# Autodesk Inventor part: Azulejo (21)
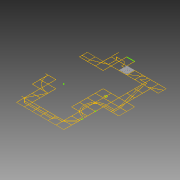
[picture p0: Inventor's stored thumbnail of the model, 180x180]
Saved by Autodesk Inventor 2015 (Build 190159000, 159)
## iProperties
Created: 2015-04
Part Number: Azulejo (21)
Material: Genérico
Document SubType Name: Modeling
Designer: Felipe
Density: 1 g/cm^3
Appearance: Padrão
Author: Felipe
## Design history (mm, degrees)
sketch "Sketch1"
  geometry: L1 (-1510, -7490)-(-1510, -6010); L2 (992.445, 7510)-(992.445, 8990); L3 (1012.445, 7510)-(1012.445, 8990); L4 (-3010, -1490)-(-3010, -10); L5 (-1510, 7490)-(-2990, 7490); L6 (-2990, 10)-(-1510, 10); L7 (-1510, -10)-(-2990, -10); L8 (-1510, -1490)-(-1510, -10); L9 (-10, 9010)-(-10, 10490); L10 (-10, 7510)-(-10, 8990); L11 (-10, 7490)-(-1490, 7490); L12 (-1490, 6010)-(-10, 6010); L13 (-10, 5990)-(-1490, 5990); L14 (-1490, -10)-(-1490, -1490); L15 (-1490, -1490)-(-10, -1490); L16 (-10, -1510)-(-1490, -1510); L17 (-10, -2990)-(-10, -1510); L18 (-10, -5990)-(-10, -4510); L19 (-1490, -7490)-(-10, -7490); L20 (10, 8990)-(10, 7510); L21 (1490, 7510)-(1490, 8990); L22 (10, 6010)-(1490, 6010); L23 (1490, 6010)-(1490, 7490); L24 (1490, 5990)-(10, 5990); L25 (4490, -6010)-(3010, -6010); L26 (10, -1510)-(10, -2990); L27 (10, -3010)-(10, -4490); L28 (10, -4510)-(10, -5990); L29 (10, -5990)-(1490, -5990); L30 (1490, -6010)-(10, -6010); L31 (10, -7490)-(1490, -7490); L32 (2990, 9010)-(2990, 10490); L33 (1510, 8990)-(1510, 7510); L34 (1510, 7510)-(2990, 7510); L35 (2990, 7490)-(1510, 7490); L36 (1510, 7490)-(1510, 6010); L37 (1510, -5990)-(2990, -5990); L38 (2990, -6010)-(1510, -6010); L39 (1510, -7490)-(2990, -7490); L40 (3010, 10490)-(3010, 9010); L41 (3010, 9010)-(4490, 9010); L42 (4490, 8990)-(3010, 8990); L43 (4490, 7490)-(3010, 7490); L44 (4490, 1510)-(4490, 2990); L45 (4490, 10)-(4490, 1490); L46 (4490, -1490)-(4490, -10); L47 (4490, -2990)-(4490, -1510); L48 (3010, -5990)-(4490, -5990); L49 (3010, -7490)-(4490, -7490); L50 (4510, 9010)-(5990, 9010); L51 (5990, 8990)-(4510, 8990); L52 (4510, 7510)-(5990, 7510); L53 (5990, 7490)-(4510, 7490); L54 (4510, 3010)-(5990, 3010); L55 (5990, 2990)-(4510, 2990); L56 (4510, 2990)-(4510, 1510); L57 (4510, 1510)-(5990, 1510); L58 (5990, 1510)-(5990, 1740.185); L59 (5990, 1760.2)-(5990, 2259.8); L60 (5990, 2279.815)-(5990, 2990); L61 (5990, 1490)-(4510, 1490); L62 (4510, 1490)-(4510, 10); L63 (4510, 10)-(5990, 10); L64 (5990, 10)-(5990, 1490)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; A1 r 250 centre (6000, 2010) between (5990, 2259.8) and (5990, 1760.2); A2 r 250 centre (6000, 2010) between (6010, 1760.2) and (6010, 2259.8); A3 r 270 centre (6000, 2010) between (5990, 2279.815) and (5990, 1740.185); A4 r 270 centre (6000, 2010) between (6010, 1740.185) and (6010, 2279.815); A5 r 3010.017 centre (0, 0) between (-1490, -2615.358) and (-346.554, -2990); A6 r 2990.017 centre (0, 0) between (-1490, -2592.316) and (-10, -2990); A7 r 3010.017 centre (0, 0) between (-2603.863, -1510) and (-1510, -2603.863); A8 r 2990.017 centre (0, 0) between (-2580.717, -1510) and (-1510, -2580.717); A9 r 3010.017 centre (0, 0) between (-2990, -346.554) and (-2615.358, -1490); A10 r 2990.017 centre (0, 0) between (-2990, -10) and (-2592.316, -1490); A11 r 2131.367 centre (7500, -1500) between (7490, 631.344) and (6010, 24.017); A12 r 2131.367 centre (7500, -1500) between (5975.983, -10) and (5368.656, -1490); A13 r 2131.367 centre (7500, -1500) between (5368.656, -1510) and (5975.983, -2990); A14 r 2131.367 centre (7500, -1500) between (6010, -3024.017) and (7190, -3608.703); A15 r 1831.367 centre (7500, -1500) between (7490.321, 331.342) and (6463.753, 10); A16 r 1831.367 centre (7500, -1500) between (6435.196, -10) and (6010, -435.196); A17 r 1831.367 centre (7500, -1500) between (5990, -463.753) and (5668.66, -1490); A18 r 1831.367 centre (7500, -1500) between (5668.66, -1510) and (5990, -2536.247); A19 r 1831.367 centre (7500, -1500) between (6010, -2564.804) and (6435.196, -2990); A20 r 1831.367 centre (7500, -1500) between (6463.753, -3010) and (7490, -3331.34); A21 r 2111.367 centre (7500, -1500) between (7490.047, 611.344) and (6024.272, 10); A22 r 2111.367 centre (7500, -1500) between (5990, -24.272) and (5388.656, -1490); A23 r 2111.367 centre (7500, -1500) between (5388.656, -1510) and (5990, -2975.728); A24 r 2111.367 centre (7500, -1500) between (6024.272, -3010) and (7210, -3591.357); A25 r 1811.367 centre (7500, -1500) between (7490.374, 311.342) and (6499.524, 10); A26 r 1811.367 centre (7500, -1500) between (6469.975, -10) and (6010, -469.975); A27 r 1811.367 centre (7500, -1500) between (5990, -499.524) and (5688.66, -1490); A28 r 1811.367 centre (7500, -1500) between (5688.66, -1510) and (5990, -2500.476); A29 r 1811.367 centre (7500, -1500) between (6010, -2530.025) and (6469.975, -2990); A30 r 1811.367 centre (7500, -1500) between (6499.524, -3010) and (7490, -3311.34); A31 r 449.871 centre (7499.449, -4060.672) between (7510, -4510.419) and (7521.546, -4510); 5 further points
  constraints: 1042 end point, 64 point on circle, 31 centre point, 13 point on line, 1 horizontal, 1 other
extrude "Extrusion1" new body sketch "Sketch1" distance "d0" = 60; taper "d1" = 0 deg
extrude "Extrusion2" new body sketch "Sketch1" distance "d2" = 60; taper "d3" = 0 deg
extrude "Extrusion3" new body sketch "Sketch1" distance "d4" = 60; taper "d5" = 0 deg
body "Solid1"
body "Solid2"
body "Solid3"
